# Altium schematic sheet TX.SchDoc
size A3; PageSetup: Record=PageOptions|CenterHorizontal=True|CenterVertical=True|PrintScale=1.01|XCorrection=1.00|YCorrection=1.00|PrintKind=2|BorderSize=5000000|LeftOffset=0|BottomOffset=0|Orientation=2|PaperLength=4200|PaperWidth=2970|Scale=100|PaperSource=7|PrintQuality=600|MediaType=1|DitherType=10|PaperKind=A3|PrintScaleMode=1
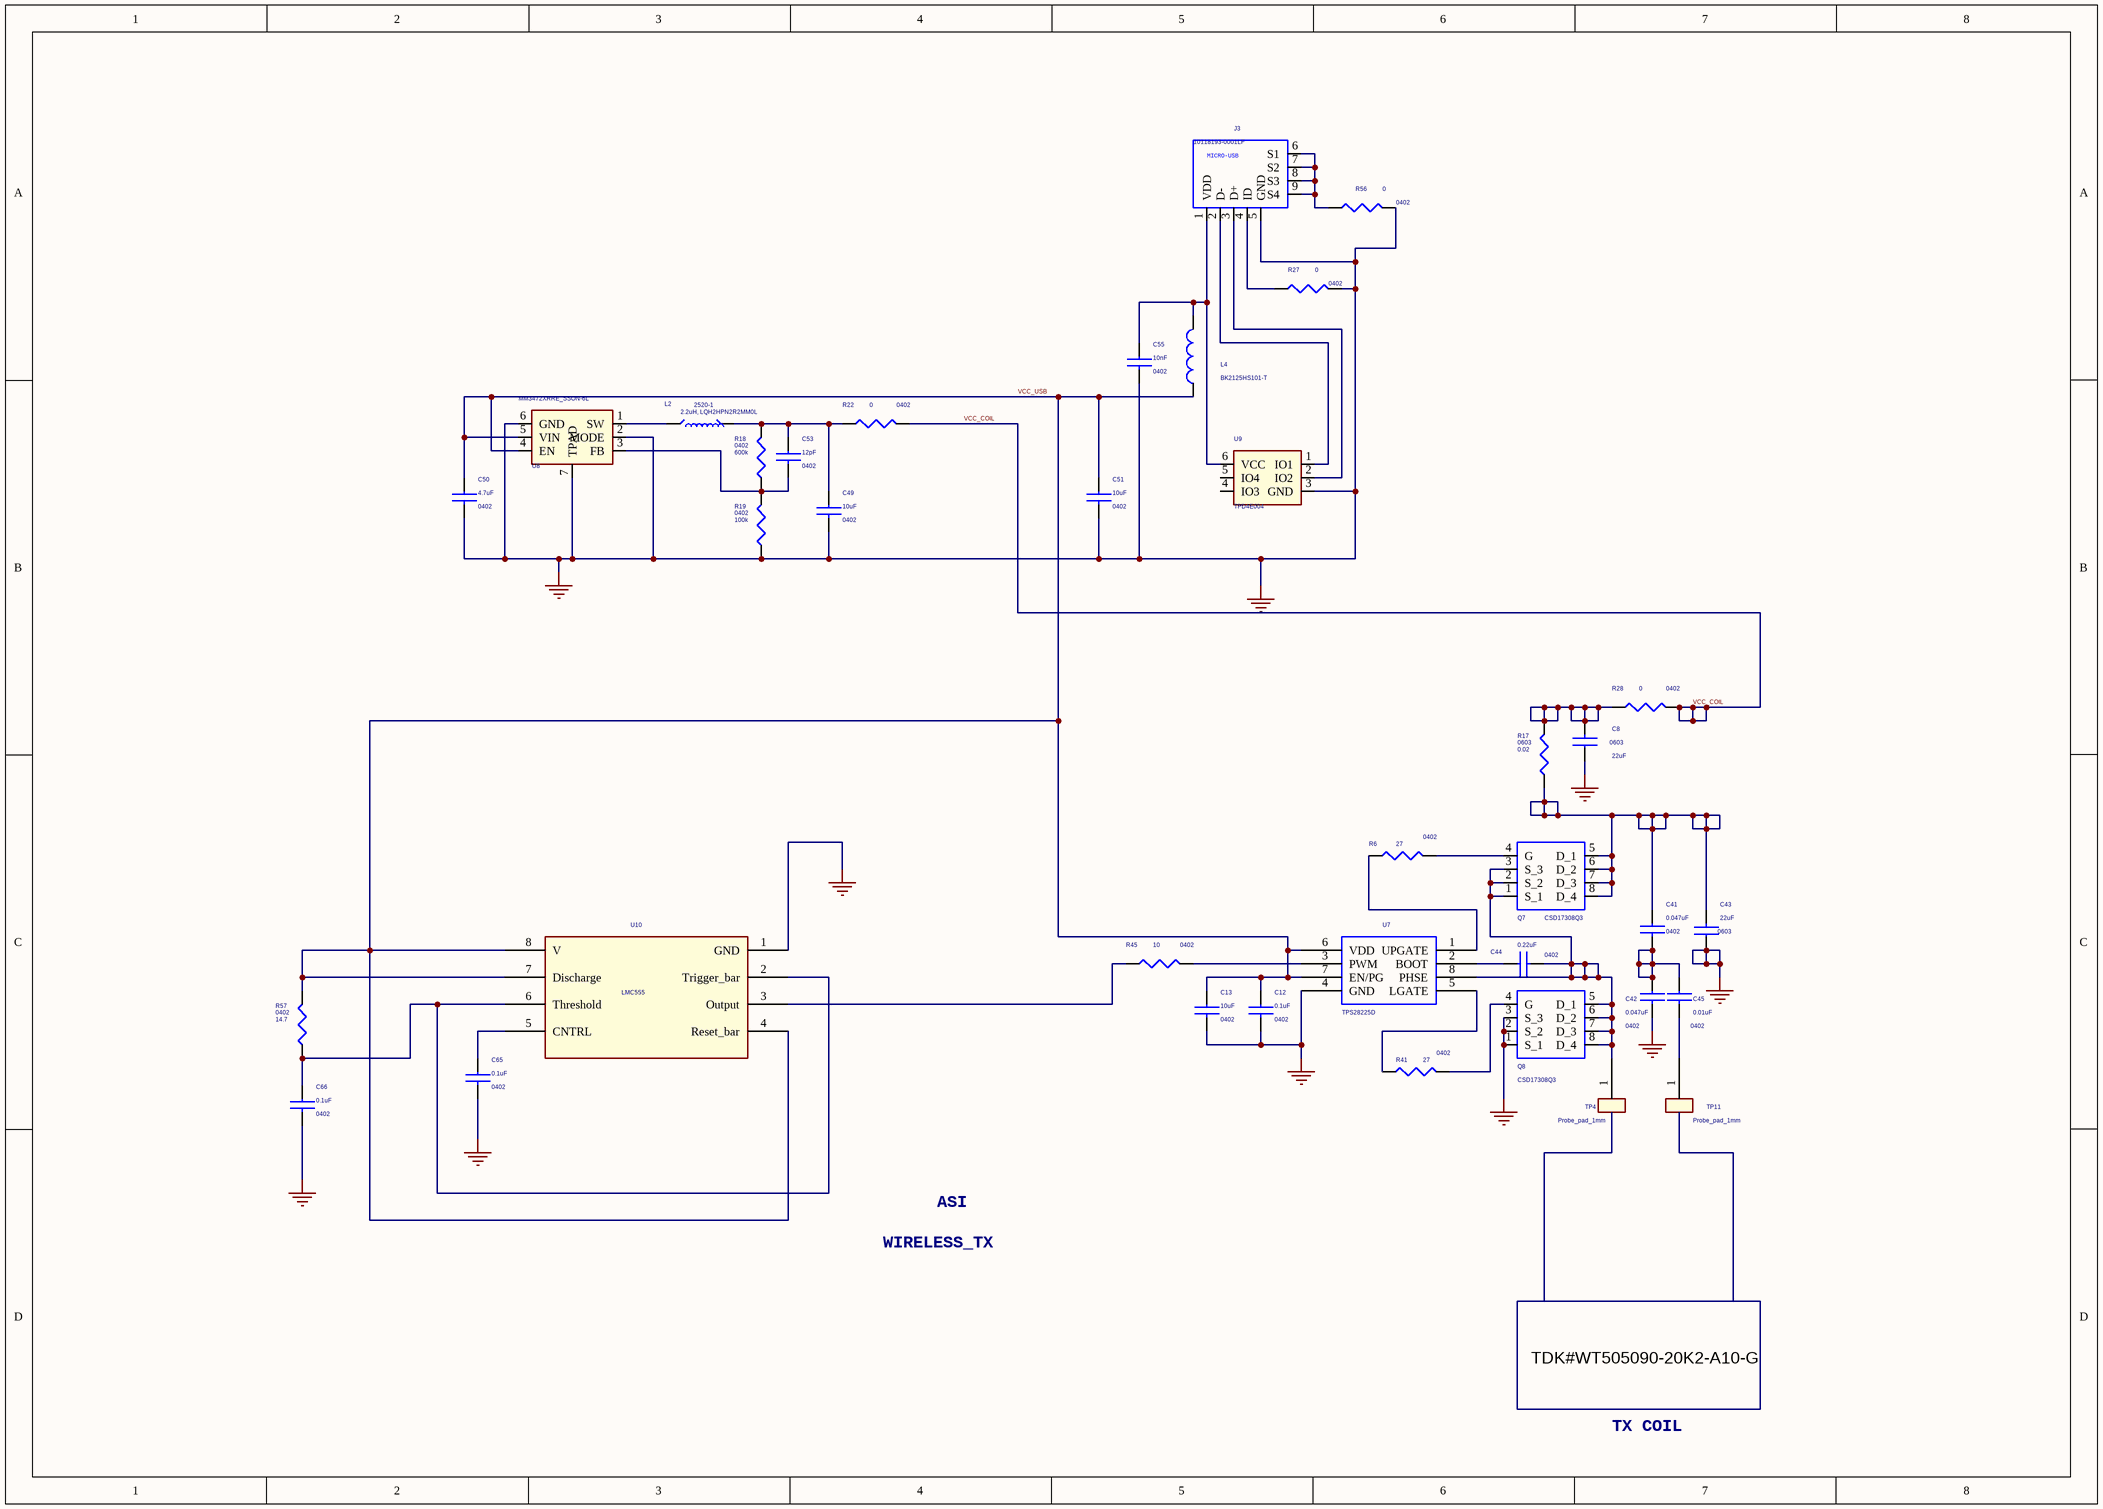
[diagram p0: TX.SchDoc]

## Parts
C8  22uF  Package: 0603  [0603CS]
C12  0.1uF  Package: 0402  [0402C]
C13  10uF  Package: 0402  [0402C]
C41  0.047uF  Package: 0402  [0402C]
C42  0.047uF  Package: 0402  [0402C]
C43  22uF  Package: 0603  [0603CS]
C44  0.22uF  Package: 0402  [0402C]
C45  0.01uF  Package: 0402  [0402C]
C49  10uF  Package: 0402  [0402C]
C50  4.7uF  Package: 0402  [0402C]
C51  10uF  Package: 0402  [0402C]
C53  12pF  Package: 0402  [0402C]
C55  10nF  Package: 0402  [0402C]
C65  0.1uF  Package: 0402  [0402C]
C66  0.1uF  Package: 0402  [0402C]
J3  10118193-0001LF  [10118193-0001LF]
L2  2.2uH, LQH2HPN2R2MM0L  [2520-1]
L4  BK2125HS101-T  [0805L]
Q7  CSD17308Q3  [SSON_3.3*3.3]
Q8  CSD17308Q3  [SSON_3.3*3.3]
R6  27  PACKAGE: 0402  [0402R]
R17  0.02  PACKAGE: 0603  [0603RS]
R18  600k  PACKAGE: 0402  [0402R]
R19  100k  PACKAGE: 0402  [0402R]
R22  0  PACKAGE: 0402  [0402R]
R27  0  PACKAGE: 0402  [0402R]
R28  0  PACKAGE: 0402  [0402R]
R41  27  PACKAGE: 0402  [0402R]
R45  10  PACKAGE: 0402  [0402R]
R56  0  PACKAGE: 0402  [0402R]
R57  14.7  PACKAGE: 0402  [0402R]
TP4  Probe_pad_1mm  [PAD]
TP11  Probe_pad_1mm  [PAD]
U7  TPS28225D  [SOIC8]
U8  MM3472XRRE_SSON-6L  [SSON-6L]
U9  TPD4E004  [SON6]
U10  LMC555  [SOIC8]

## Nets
GND: C8.1 C12.2 C13.2 C42.2 C43.1 C49.2 C50.2 C51.2 C55.2 C65.2 C66.2 J3.5(GND) Q8.1(S_1) Q8.2(S_2) Q8.3(S_3) R19.1 R27.2 R56.2 U7.4(GND) U8.2(MODE) U8.6(GND) U8.7(TPAD) U9.3(GND) U10.1(GND)
VCC_COIL: R22.2 R28.2
VCC_USB: C12.1 C13.1 C50.1 C51.1 L4.1 R57.2 U7.6(VDD) U7.7(EN/PG) U8.4(EN) U8.5(VIN) U10.4(Reset_bar) U10.7(Discharge) U10.8(V)
NetC8_2: C8.2 R17.2 R28.1
NetC41_1: C41.1 C43.2 Q7.5(D_1) Q7.6(D_2) Q7.7(D_3) Q7.8(D_4) R17.1
NetC41_2: C41.2 C42.1 C45.1
NetC44_1: C44.1 U7.2(BOOT)
NetC44_2: C44.2 Q7.1(S_1) Q7.2(S_2) Q7.3(S_3) Q8.5(D_1) Q8.6(D_2) Q8.7(D_3) Q8.8(D_4) TP4.1 U7.8(PHSE)
NetC45_2: C45.2 TP11.1
NetC49_1: C49.1 C53.1 L2.2 R18.2 R22.1
NetC53_2: C53.2 R18.1 R19.2 U8.3(FB)
NetC55_1: C55.1 J3.1(VDD) L4.2 U9.6(VCC)
NetC65_1: C65.1 U10.5(CNTRL)
NetC66_1: C66.1 R57.1 U10.2(Trigger_bar) U10.6(Threshold)
NetJ3_2: J3.2(D-) U9.1(IO1)
NetJ3_3: J3.3(D+) U9.2(IO2)
NetJ3_4: J3.4(ID) R27.1
NetJ3_6: J3.6(S1) J3.7(S2) J3.8(S3) J3.9(S4) R56.1
NetL2_1: L2.1 U8.1(SW)
NetQ7_4: Q7.4(G) R6.2
NetQ8_4: Q8.4(G) R41.2
NetR6_1: R6.1 U7.1(UPGATE)
NetR41_1: R41.1 U7.5(LGATE)
NetR45_1: R45.1 U10.3(Output)
NetR45_2: R45.2 U7.3(PWM)

Not connected (* = marked no-connect by the designer): U9 4(IO3) 5(IO4)

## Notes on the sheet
- WIRELESS_TX
- ASI
- TDK#WT505090-20K2-A10-G
- TX COIL

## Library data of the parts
C8 C12 C13 C43 C44 C49-C51 C53 C55 C65 C66 = CAP_2.2nF_X7R_0603: Desc: Cap, Ceramic, X7R; GATAN: 100776; MFG: STD; MFG#: C0603C104M5RACTU; Tolerance: 20; Voltage: 50V
C41 C42 C45 = CAP_2.2nF_X7R_0603: Desc: Cap, Ceramic, C0G, 1%; GATAN: 100776; MFG: STD; MFG#: C0603C104M5RACTU; Tolerance: 20; Voltage: 50V
J3 = 10118193-0001LF_MUSB_1: Number devices in Package: 1; OriginalSymbolOrigin: (0,0); DESC: Micro USB connector; MFG: FCI
L2 = MLZ1005M2R2W_Ind402_0: MFG: MURATA; MFG#: CRCW060310K0FKEA; GATAN: 11135; DESC: Inductor 2.2uH 2520mm
L4 = INDUCTOR/SM: MFG: Taiyo Yuden; DESC: Multilayer chip bead inductors (BK series)
Q7 Q8 = CSD17308Q3: Number devices in Package: 1; OriginalSymbolOrigin: (0,0); DESC: NFET; MFG: TI
R6 R17-R19 R41 R57 = RES_10K_0603_THK_1%: MFG: STD; MFG#: CRCW060310K0FKEA; GATAN: 11135; DESC: RESISTOR, 1/16W, 1%
R22 R27 R28 R45 R56 = RES_1oHM_0603: GATAN: 11135; MFG#: CRCW060310K0FKEA; MFG: STD; DESC: RESISTOR, 1/16W, 1%
TP4 TP11 = TEST POINT: DESC: DNI
U7 = sn74lvc1g74dqer_0: Number devices in Package: 1; OriginalSymbolOrigin: (0,0); DESC: DRIVER; MFG: TI
U8 = MM3472XRRE-6P_4: DESC: DCDC; MFG: MITSUMI
U9 = TPD4E004: MFG: TI; DESC: ESD protection for high-speed Interfaces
